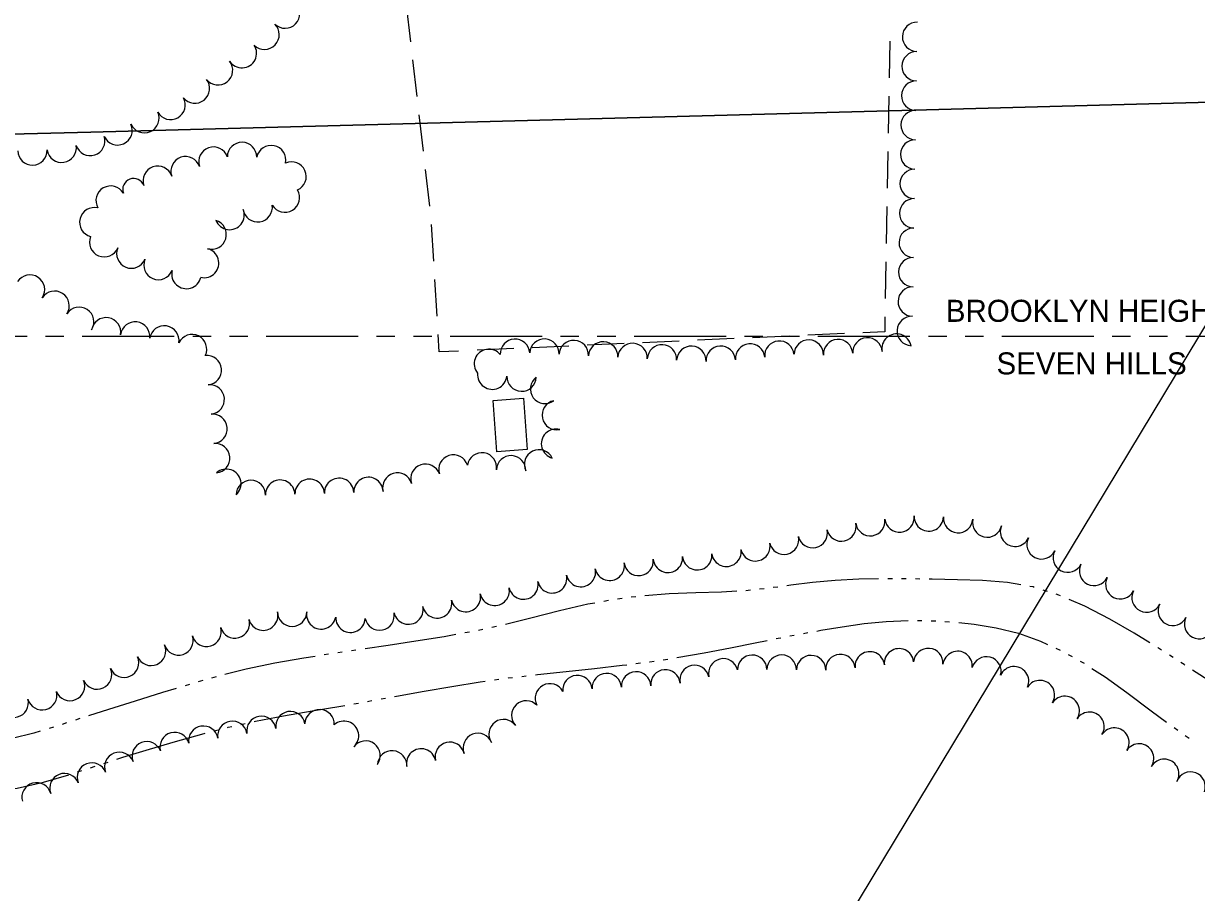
# Model space of a CAD drawing. Extents: x -25029 to 2274964, y -81170 to 687028.
# Drawn here: x -14288 to -13491, y -67223 to -66632 of the extents above; entities that cross this region are included whole.
import ezdxf

# ---------------------------------------------------------------- set-up
doc = ezdxf.new("R2010")
doc.units = 0
for name, color, linetype in [('BLDG', 7, 'Continuous'), ('DIVISIONS', 7, 'Continuous'), ('DV_X_Corp_Line', 7, 'Continuous'), ('RECREATION', 7, 'Continuous'), ('SC_Scratch18', 7, 'Continuous'), ('TREES', 7, 'Continuous'), ('WATER', 7, 'Continuous')]:
    doc.layers.add(name, color=color, linetype=linetype)

msp = doc.modelspace()

# ---------------------------------------------------------------- linework, layer by layer
at = {"layer": 'BLDG'}
msp.add_lwpolyline([(-13948.56, -66886.81), (-13945.99, -66921.64), (-13966.57, -66923.15), (-13969.13, -66888.32)], close=True, dxfattribs=at)
at = {"layer": 'DIVISIONS'}
for p, q in [((-14298.36, -66844.66), (-14285.86, -66844.66)), ((-14273.36, -66844.66), (-14260.86, -66844.66)), ((-14248.36, -66844.66), (-14185.86, -66844.66)), ((-14173.36, -66844.66), (-14160.86, -66844.66)), ((-14148.36, -66844.66), (-14135.86, -66844.66)), ((-14123.36, -66844.66), (-14060.86, -66844.66)), ((-14048.36, -66844.66), (-14035.86, -66844.66)), ((-14023.36, -66844.66), (-14010.86, -66844.66)), ((-13998.36, -66844.66), (-13935.86, -66844.66)), ((-13923.36, -66844.66), (-13910.86, -66844.66)), ((-13898.36, -66844.66), (-13885.86, -66844.66)), ((-13873.36, -66844.66), (-13810.86, -66844.66)), ((-13798.36, -66844.66), (-13785.86, -66844.66)), ((-13773.36, -66844.66), (-13760.86, -66844.66)), ((-13748.36, -66844.66), (-13685.86, -66844.66)), ((-13673.36, -66844.66), (-13660.86, -66844.66)), ((-13648.36, -66844.66), (-13635.86, -66844.66)), ((-13623.36, -66844.66), (-13560.86, -66844.66)), ((-13548.36, -66844.66), (-13535.86, -66844.66)), ((-13523.36, -66844.66), (-13510.86, -66844.66)), ((-13498.36, -66844.66), (-13435.86, -66844.66))]:
    msp.add_line(p, q, dxfattribs=at)
at = {"layer": 'DV_X_Corp_Line'}
for p, q in [((-13452.42, -66684.8), (-13682.9, -66690.94)), ((-13452.42, -66684.8), (-13682.9, -66690.94)), ((-13682.9, -66690.94), (-13452.42, -66684.8)), ((-13682.9, -66690.94), (-13452.42, -66684.8)), ((-13682.9, -66690.94), (-14242.66, -66705.86)), ((-13682.9, -66690.94), (-14242.66, -66705.86)), ((-14242.66, -66705.86), (-13682.9, -66690.94)), ((-14242.66, -66705.86), (-13682.9, -66690.94)), ((-14242.66, -66705.86), (-14396.63, -66709.96)), ((-14242.66, -66705.86), (-14396.63, -66709.96)), ((-14396.63, -66709.96), (-14242.66, -66705.86)), ((-14396.63, -66709.96), (-14242.66, -66705.86))]:
    msp.add_line(p, q, dxfattribs=at)
at = {"layer": 'RECREATION'}
for p, q in [((-14025.09, -66644.4), (-14027.96, -66619.56)), ((-13699.53, -66644.02), (-13699.97, -66669.01)), ((-14020.8, -66681.65), (-14023.66, -66656.82)), ((-13700.19, -66681.51), (-13700.63, -66706.51)), ((-14016.5, -66718.9), (-14019.36, -66694.07)), ((-13700.85, -66719.01), (-13701.29, -66744)), ((-14012.2, -66756.16), (-14015.07, -66731.32)), ((-13701.51, -66756.5), (-13701.95, -66781.5)), ((-14009.51, -66793.55), (-14011.02, -66768.6)), ((-13702.17, -66794), (-13702.61, -66818.99)), ((-14007.25, -66830.98), (-14008.75, -66806.03)), ((-13767.81, -66844.53), (-13792.79, -66845.66)), ((-13730.35, -66842.85), (-13755.32, -66843.97)), ((-13955.12, -66852.95), (-13980.1, -66854.08)), ((-13917.66, -66851.27), (-13942.64, -66852.39)), ((-13880.2, -66849.58), (-13905.17, -66850.71)), ((-13842.74, -66847.9), (-13867.71, -66849.02)), ((-13805.27, -66846.22), (-13830.25, -66847.34))]:
    msp.add_line(p, q, dxfattribs=at)
for points in [[(-13702.83, -66831.49), (-13703.01, -66841.62), (-13717.86, -66842.29)], [(-13992.59, -66854.64), (-14005.78, -66855.23), (-14006.49, -66843.46)]]:
    msp.add_lwpolyline(points, dxfattribs=at)
at = {"layer": 'SC_Scratch18'}
msp.add_line((-12949.9, -65949.35), (-15781.15, -70645.51), dxfattribs=at)
at = {"layer": 'TREES'}
for centre, radius, start, end in [((-14110.57, -66625.25), 10, 225.91856, 45.91856), ((-14124.5, -66639.6), 10, 225.76207, 45.76207), ((-13680.99, -66641.08), 10, 89.05938, 269.05938), ((-14139.88, -66652.18), 10, 212.84496, 32.84496), ((-13681.32, -66661.08), 10, 89.05938, 269.05938), ((-14156.13, -66663.8), 10, 218.278, 38.278), ((-14171.81, -66676.22), 10, 218.50112, 38.50112), ((-13681.64, -66681.07), 10, 89.05938, 269.05938), ((-14188.36, -66687.33), 10, 209.20841, 29.20841), ((-14206.2, -66696.35), 10, 204.4499, 24.4499), ((-13681.97, -66701.07), 10, 89.05938, 269.05938), ((-14224.4, -66704.62), 10, 204.4499, 24.4499), ((-14243.01, -66711.88), 10, 198.15081, 18.15081), ((-14262.4, -66716.5), 10, 188.66313, 8.66313), ((-14159.26, -66725.94), 10, 18.99746, 198.99746), ((-14139.8, -66722.77), 10, 359.48528, 179.48528), ((-14120.01, -66724.88), 10, 348.34598, 168.34598), ((-13682.3, -66721.07), 10, 89.05938, 269.05938), ((-14282.28, -66718.28), 10, 181.56377, 1.56377), ((-14178.17, -66732.45), 10, 18.99746, 198.99746), ((-14197.08, -66738.96), 10, 18.99746, 198.99746), ((-14106.17, -66736.05), 10, 293.88784, 113.88784), ((-13682.63, -66741.07), 10, 89.05938, 269.05938), ((-14213.49, -66744.82), 7.43, 20.52647, 200.52647), ((-14229.11, -66752.43), 10, 30.00494, 210.00494), ((-14110.7, -66750.32), 10, 210.85512, 30.85512), ((-14240.23, -66767.12), 10, 75.74566, 255.74566), ((-14129.17, -66756.93), 10, 188.53082, 8.53082), ((-13682.96, -66761.06), 10, 89.05938, 269.05938), ((-14148.33, -66762.17), 10, 202.06303, 22.06303), ((-14160.45, -66775.51), 10, 253.43899, 73.43899), ((-13683.29, -66781.06), 10, 89.05938, 269.05938), ((-14233.47, -66780.68), 10, 157.23292, 337.23292), ((-14215.03, -66788.42), 10, 157.23292, 337.23292), ((-14165.59, -66794.83), 10, 256.74402, 76.74402), ((-14196.59, -66796.16), 10, 157.23292, 337.23292), ((-13683.61, -66801.06), 10, 89.05938, 269.05938), ((-14283.95, -66812.94), 10, 326.84152, 146.84152), ((-14177.63, -66802.3), 10, 166.89344, 346.89344), ((-13683.94, -66821.06), 10, 89.05938, 269.05938), ((-14267.21, -66823.88), 10, 326.84152, 146.84152), ((-14250.46, -66834.82), 10, 326.84152, 146.84152), ((-14232.23, -66841.96), 10, 350.37657, 170.37657), ((-14212.44, -66844.8), 10, 353.29779, 173.29779), ((-13684.62, -66841.04), 10, 87.05449, 267.05449), ((-14192.63, -66847.51), 10, 351.09899, 171.09899), ((-14173.75, -66853.43), 10, 334.10621, 154.10621), ((-13694.94, -66853.01), 10, 11.45715, 191.45715), ((-13954.28, -66856.48), 10, 3.27708, 183.27708), ((-13934.31, -66856.4), 10, 357.16213, 177.16213), ((-13914.34, -66857.39), 10, 357.16213, 177.16213), ((-13894.36, -66858.38), 10, 357.16213, 177.16213), ((-13874.38, -66859.37), 10, 357.16213, 177.16213), ((-13854.41, -66860.36), 10, 357.16213, 177.16213), ((-13834.43, -66861.35), 10, 357.16213, 177.16213), ((-13814.46, -66861.24), 10, 3.45477, 183.45477), ((-13794.53, -66859.7), 10, 5.38952, 185.38952), ((-13774.62, -66857.82), 10, 5.38952, 185.38952), ((-13754.66, -66857.13), 10, 358.57538, 178.57538), ((-13734.68, -66856.8), 10, 3.328, 183.328), ((-13714.72, -66855.61), 10, 3.4983, 183.4983), ((-14163.74, -66867.74), 10, 275.82431, 95.82431), ((-13971.99, -66863.4), 10, 39.44515, 219.44515), ((-13969.76, -66870.72), 10, 174.43997, 354.43997), ((-13949.81, -66872.04), 10, 178.00541, 358.00541), ((-13933.86, -66880.42), 10, 126.53628, 306.53628), ((-14161.79, -66887.65), 10, 275.37679, 95.37679), ((-13925.88, -66898.25), 10, 101.70304, 281.70304), ((-14159.92, -66907.56), 10, 275.37679, 95.37679), ((-13926.39, -66917.72), 10, 75.28487, 255.28487), ((-14158.04, -66927.47), 10, 275.37679, 95.37679), ((-13976.78, -66933.77), 10, 350.83577, 170.83577), ((-13937.93, -66931.76), 10, 25.94086, 205.94086), ((-14015.18, -66941.45), 10, 18.72122, 198.72122), ((-13996.18, -66935.21), 10, 17.65427, 197.65427), ((-13956.91, -66935.75), 10, 357.78697, 177.78697), ((-14150.47, -66944.91), 10, 311.54611, 131.54611), ((-14053.88, -66950.46), 10, 1.76139, 181.76139), ((-14034.26, -66947.41), 10, 15.9337, 195.9337), ((-14133.84, -66952.5), 10, 359.37735, 179.37735), ((-14113.85, -66952.31), 10, 1.76139, 181.76139), ((-14093.86, -66951.69), 10, 1.76139, 181.76139), ((-14073.87, -66951.08), 10, 1.76139, 181.76139), ((-13732.47, -66973.94), 10, 192.96036, 12.96036), ((-13712.83, -66970.27), 10, 188.16966, 8.16966), ((-13692.98, -66967.79), 10, 186.09372, 6.09372), ((-13673.05, -66967.09), 10, 177.94751, 357.94751), ((-13653.08, -66968.21), 10, 175.59144, 355.59144), ((-13633.37, -66971.23), 10, 167.01044, 347.01044), ((-13751.96, -66978.42), 10, 192.96036, 12.96036), ((-13614.47, -66977.51), 10, 156.21381, 336.21381), ((-13790.94, -66987.39), 10, 192.96036, 12.96036), ((-13771.45, -66982.91), 10, 192.96036, 12.96036), ((-13596.4, -66986.06), 10, 153.13896, 333.13896), ((-13870.24, -66997.34), 10, 186.85952, 6.85952), ((-13850.35, -66995.26), 10, 185.052, 5.052), ((-13830.42, -66993.5), 10, 185.052, 5.052), ((-13810.57, -66991.13), 10, 188.58471, 8.58471), ((-13578.56, -66995.1), 10, 153.13896, 333.13896), ((-13909.48, -67004.91), 10, 192.27496, 12.27496), ((-13889.94, -67000.66), 10, 192.27496, 12.27496), ((-13560.72, -67004.14), 10, 153.13896, 333.13896), ((-13948.56, -67013.41), 10, 192.27496, 12.27496), ((-13929.02, -67009.16), 10, 192.27496, 12.27496), ((-13542.88, -67013.17), 10, 153.13896, 333.13896), ((-13987.65, -67021.92), 10, 192.27496, 12.27496), ((-13968.11, -67017.67), 10, 192.27496, 12.27496), ((-13525.03, -67022.21), 10, 153.13896, 333.13896), ((-14026.73, -67030.42), 10, 192.27496, 12.27496), ((-14007.19, -67026.17), 10, 192.27496, 12.27496), ((-13507.19, -67031.25), 10, 153.13896, 333.13896), ((-14125.42, -67034.51), 10, 195.20395, 15.20395), ((-14105.77, -67031.86), 10, 180.10476, 0.10476), ((-14085.94, -67033.68), 10, 169.43849, 349.43849), ((-14066.12, -67035.96), 10, 177.45397, 357.45397), ((-14046.32, -67034.47), 10, 191.10389, 11.10389), ((-13489.35, -67040.28), 10, 153.13896, 333.13896), ((-14163.89, -67045.47), 10, 196.60897, 16.60897), ((-14144.69, -67039.87), 10, 195.92179, 15.92179), ((-14182.99, -67051.39), 10, 197.80119, 17.80119), ((-14201.67, -67058.47), 10, 203.70678, 23.70678), ((-13713.17, -67069.02), 10, 6.01965, 186.01965), ((-13693.28, -67066.92), 10, 6.01965, 186.01965), ((-13673.37, -67066.72), 10, 355.12585, 175.12585), ((-13653.47, -67068.71), 10, 353.46311, 173.46311), ((-14219.98, -67066.51), 10, 203.70678, 23.70678), ((-13832.27, -67078.22), 10, 12.45323, 192.45323), ((-13812.77, -67073.76), 10, 13.29323, 193.29323), ((-13793.04, -67071.29), 10, 1.00295, 181.00295), ((-13773.05, -67071.25), 10, 359.18763, 179.18763), ((-13753.05, -67071.54), 10, 359.18763, 179.18763), ((-13733.08, -67070.87), 10, 4.62039, 184.62039), ((-13633.88, -67072.45), 10, 344.90672, 164.90672), ((-14238.29, -67074.55), 10, 203.70678, 23.70678), ((-13911.86, -67085.13), 10, 5.01798, 185.01798), ((-13891.92, -67083.73), 10, 3.05662, 183.05662), ((-13871.94, -67082.66), 10, 3.05662, 183.05662), ((-13852, -67081.25), 10, 5.02456, 185.02456), ((-13615.08, -67079.09), 10, 336.233, 156.233), ((-14256.71, -67082.34), 10, 202.12752, 22.12752), ((-13930.63, -67090.74), 10, 28.24961, 208.24961), ((-13597.5, -67088.5), 10, 327.42775, 147.42775), ((-14294.99, -67093.75), 10, 194.77125, 14.77125), ((-14275.65, -67088.65), 10, 194.77125, 14.77125), ((-13580.64, -67099.27), 10, 327.42775, 147.42775), ((-14106.93, -67109.61), 10, 9.52926, 189.52926), ((-14087.08, -67108.33), 10, 357.82699, 177.82699), ((-13946.68, -67102.38), 10, 43.6613, 223.6613), ((-13563.79, -67110.04), 10, 327.42775, 147.42775), ((-14146.38, -67116.23), 10, 9.52926, 189.52926), ((-14126.66, -67112.92), 10, 9.52926, 189.52926), ((-14070.48, -67116.22), 10, 311.35808, 131.35808), ((-13962.08, -67115.06), 10, 35.27794, 215.27794), ((-14185.61, -67123.85), 10, 15.36054, 195.36054), ((-14166.1, -67119.54), 10, 9.52926, 189.52926), ((-13979.55, -67124.48), 10, 21.41034, 201.41034), ((-13546.93, -67120.8), 10, 327.42775, 147.42775), ((-14204.57, -67130.11), 10, 21.18352, 201.18352), ((-14055.82, -67129.66), 10, 323.59017, 143.59017), ((-13998.57, -67130.51), 10, 13.73343, 193.73343), ((-13530.08, -67131.57), 10, 327.42775, 147.42775), ((-14223.22, -67137.34), 10, 21.18352, 201.18352), ((-14037.8, -67136.36), 10, 355.60027, 175.60027), ((-14018.06, -67135.01), 10, 12.25828, 192.25828), ((-14241.87, -67144.56), 10, 21.18352, 201.18352), ((-13513.06, -67142.06), 10, 329.27151, 149.27151), ((-14260.52, -67151.79), 10, 21.18352, 201.18352), ((-13495.1, -67150.69), 10, 339.4387, 159.4387), ((-14279.48, -67158.07), 10, 15.4969, 195.4969)]:
    msp.add_arc(centre, radius, start, end, dxfattribs=at)
at = {"layer": 'WATER'}
for p, q in [((-13697.82, -67009.49), (-13700.94, -67009.49)), ((-13688.44, -67009.51), (-13691.57, -67009.5)), ((-13679.07, -67009.64), (-13682.19, -67009.59)), ((-13784.95, -67016.25), (-13788.06, -67016.58)), ((-13775.66, -67015.06), (-13778.75, -67015.49)), ((-13592.39, -67018.12), (-13595.37, -67017.18)), ((-13890.81, -67024.28), (-13893.89, -67024.83)), ((-13881.55, -67022.85), (-13884.65, -67023.24)), ((-13872.25, -67021.69), (-13875.35, -67022.07)), ((-13976.06, -67043.87), (-13979.12, -67044.51)), ((-13966.89, -67041.94), (-13969.95, -67042.58)), ((-13680.81, -67037.85), (-13677.68, -67037.88)), ((-13671.43, -67037.96), (-13668.31, -67038.13)), ((-13662.07, -67038.48), (-13658.95, -67038.65)), ((-13985.25, -67045.73), (-13988.32, -67046.28)), ((-13767.52, -67048.35), (-13764.45, -67047.76)), ((-13758.3, -67046.63), (-13755.23, -67046.07)), ((-14071.67, -67059.37), (-14074.76, -67059.83)), ((-14062.4, -67057.99), (-14065.49, -67058.45)), ((-13586.67, -67056.65), (-13583.83, -67057.96)), ((-14080.94, -67060.77), (-14084.03, -67061.25)), ((-13872.07, -67067.09), (-13868.98, -67066.69)), ((-13853.51, -67064.47), (-13850.42, -67064)), ((-13578.3, -67060.86), (-13575.57, -67062.38)), ((-13506.9, -67063.05), (-13509.53, -67061.36)), ((-14157.5, -67076.06), (-14160.51, -67076.92)), ((-13949.71, -67075.81), (-13946.61, -67075.44)), ((-14175.53, -67081.23), (-14178.52, -67082.14)), ((-14166.52, -67078.64), (-14169.52, -67079.5)), ((-13968.3, -67078.21), (-13965.21, -67077.78)), ((-14045.34, -67091.16), (-14042.27, -67090.6)), ((-14063.8, -67094.45), (-14060.72, -67093.91)), ((-14259.01, -67107.45), (-14261.98, -67108.42)), ((-14250.1, -67104.53), (-14253.07, -67105.5)), ((-14140.64, -67108.48), (-14137.59, -67107.79)), ((-14267.93, -67110.31), (-14270.92, -67111.22)), ((-14158.87, -67112.88), (-14155.84, -67112.1)), ((-13506.39, -67110.56), (-13503.87, -67112.41)), ((-13498.76, -67116), (-13496.19, -67117.77)), ((-14251.61, -67140.8), (-14248.64, -67139.83)), ((-14242.7, -67137.9), (-14239.73, -67136.93)), ((-14233.78, -67135.01), (-14230.8, -67134.05))]:
    msp.add_line(p, q, dxfattribs=at)
for points in [[(-13707.19, -67009.53), (-13720.7, -67009.79), (-13736.63, -67010.57), (-13752.01, -67011.92), (-13766.89, -67013.84), (-13769.46, -67014.2)], [(-13610.53, -67013.52), (-13619.54, -67011.9), (-13636.63, -67010.57), (-13653.65, -67010.1), (-13670.67, -67009.76), (-13672.82, -67009.73)], [(-13803.62, -67017.91), (-13813.91, -67018.47), (-13831.41, -67019), (-13849.4, -67019.71), (-13866.04, -67020.98)], [(-13794.28, -67017.25), (-13797.29, -67017.57), (-13797.38, -67017.58)], [(-13601.33, -67015.3), (-13602.22, -67015.02), (-13604.38, -67014.63)], [(-13583.49, -67021.05), (-13584.64, -67020.56), (-13586.43, -67020)], [(-13900.04, -67025.94), (-13904.75, -67026.79), (-13923.96, -67031.27), (-13943.5, -67036.29), (-13960.79, -67040.56)], [(-13522.73, -67053), (-13533.47, -67046.34), (-13549.98, -67036.86), (-13567.09, -67028.08), (-13577.75, -67023.51)], [(-13749.07, -67044.97), (-13746.49, -67044.5), (-13731.83, -67042.04), (-13716.92, -67039.94), (-13701.91, -67038.45), (-13687.06, -67037.81)], [(-13652.73, -67039.19), (-13642.13, -67040.26), (-13627.21, -67042.72), (-13612.19, -67046.51), (-13597.08, -67051.89), (-13592.35, -67054.05)], [(-13994.48, -67047.39), (-14002.45, -67048.82), (-14021.7, -67051.9), (-14040.56, -67054.76), (-14056.22, -67057.07)], [(-13844.24, -67063.06), (-13844.19, -67063.05), (-13825.78, -67059.78), (-13807.9, -67056.31), (-13791.04, -67052.92), (-13782.86, -67051.31)], [(-13776.73, -67050.1), (-13775.52, -67049.86), (-13773.66, -67049.51)], [(-13514.78, -67057.97), (-13516.94, -67056.58), (-13517.41, -67056.29)], [(-14090.21, -67062.2), (-14097.74, -67063.37), (-14117.45, -67066.8), (-14137.07, -67070.87), (-14151.45, -67074.5)], [(-13940.4, -67074.7), (-13939.09, -67074.55), (-13919.6, -67072.48), (-13900.32, -67070.46), (-13881.38, -67068.3), (-13878.27, -67067.9)], [(-13862.78, -67065.88), (-13862.71, -67065.87), (-13859.69, -67065.41)], [(-13570.1, -67065.41), (-13567.43, -67066.9), (-13567.37, -67066.94)], [(-13499.02, -67068.13), (-13499.51, -67067.81), (-13501.65, -67066.43)], [(-13562.14, -67070.35), (-13553.18, -67076.2), (-13538.39, -67086.86), (-13521.87, -67099.19), (-13511.43, -67106.86)], [(-13441.64, -67105.99), (-13443.54, -67104.71), (-13461.58, -67092.65), (-13480.71, -67080.06), (-13493.78, -67071.54)], [(-14184.5, -67083.96), (-14193.95, -67086.84), (-14212.42, -67092.56), (-14230.57, -67098.25), (-14244.15, -67102.61)], [(-14036.12, -67089.48), (-14034.83, -67089.25), (-14016.08, -67085.87), (-13997.13, -67082.6), (-13977.96, -67079.56), (-13974.49, -67079.08)], [(-13959.02, -67076.92), (-13958.6, -67076.86), (-13955.92, -67076.54)], [(-14131.49, -67106.42), (-14130.77, -67106.26), (-14111.61, -67102.6), (-14092.08, -67099.26), (-14072.63, -67096), (-14069.95, -67095.53)], [(-14054.56, -67092.83), (-14053.59, -67092.66), (-14051.49, -67092.28)], [(-14276.9, -67113.04), (-14281.28, -67114.38), (-14295.94, -67117.95), (-14308.99, -67119.71), (-14320.68, -67119.9), (-14331.37, -67118.91), (-14338.48, -67117.54)], [(-14224.85, -67132.14), (-14220.72, -67130.81), (-14202.78, -67125.27), (-14184.95, -67119.99), (-14167.19, -67115.01), (-14164.92, -67114.43)], [(-14149.78, -67110.55), (-14149.23, -67110.41), (-14146.74, -67109.85)], [(-14318.8, -67153.22), (-14309.69, -67153.51), (-14292.53, -67151.72), (-14274.84, -67147.82), (-14257.56, -67142.72)]]:
    msp.add_lwpolyline(points, dxfattribs=at)

# ---------------------------------------------------------------- texts
at = {"layer": 'DIVISIONS'}
for s, p in [('BROOKLYN HEIGHTS', (-13661.51, -66834.82)), ('SEVEN HILLS', (-13627.04, -66870.57))]:
    msp.add_text(s, height=15, dxfattribs=at).set_placement(p)

doc.saveas('drawing.dxf')
